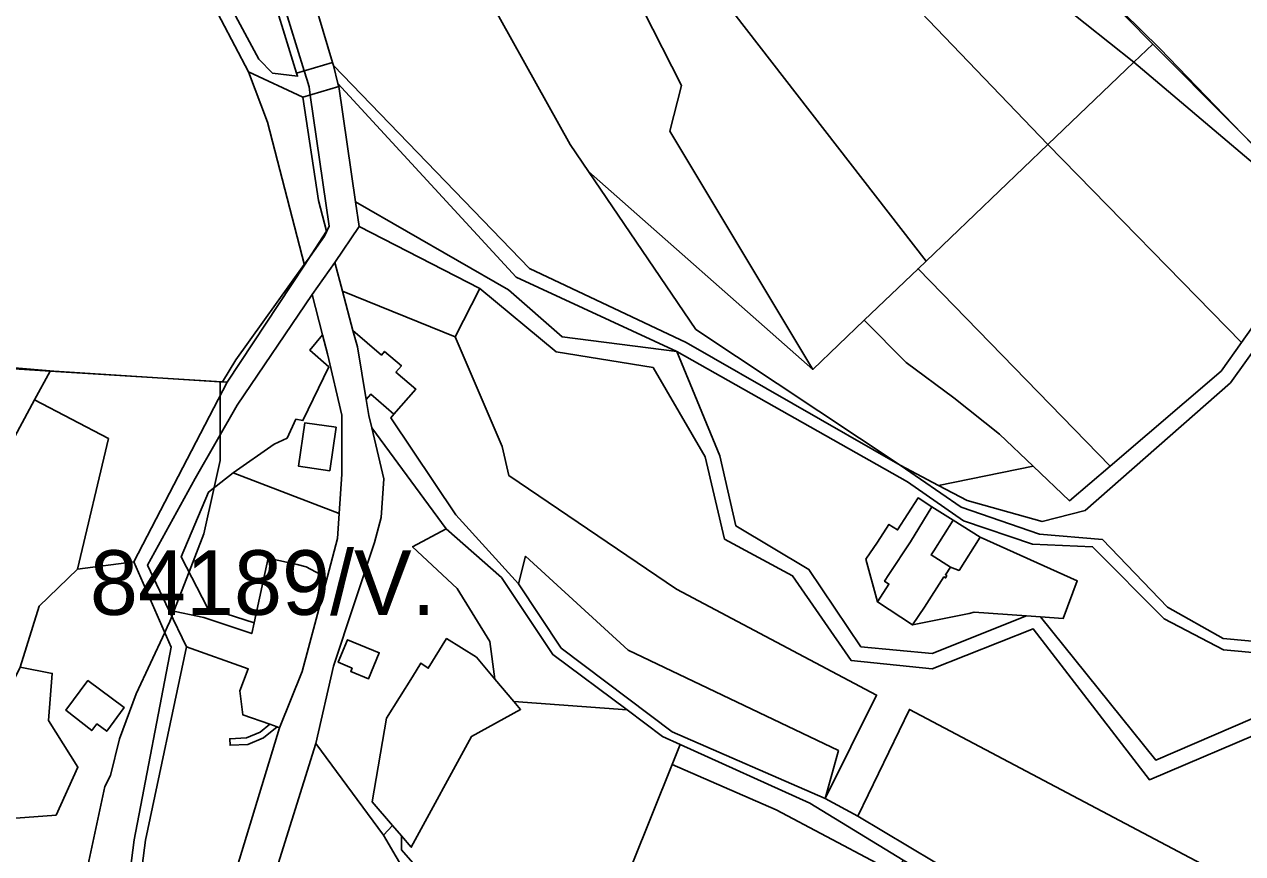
# Model space of a CAD drawing. Extents: x -477304 to -465429, y -1159113 to -1149210.
# Drawn here: x -471795.4 to -471512.5, y -1157437.1 to -1157244.4 of the extents above; entities that cross this region are included whole.
import ezdxf

# ---------------------------------------------------------------- set-up
doc = ezdxf.new("R2010")
doc.units = 0
for name, color, linetype in [('BPEJ_s', 7, 'Continuous'), ('orna_s', 7, 'Continuous'), ('ostatni_s', 7, 'Continuous'), ('PUPFL_s', 7, 'Continuous'), ('trav_porost_s', 7, 'Continuous'), ('voda_s', 7, 'Continuous')]:
    doc.layers.add(name, color=color, linetype=linetype)

msp = doc.modelspace()

# ---------------------------------------------------------------- linework, layer by layer
at = {"layer": 'BPEJ_s'}
for points in [[(-471595.75, -1157222.6), (-471575.33, -1157220.26), (-471562.35, -1157219.83), (-471553.07, -1157228.99), (-471531.73, -1157250.04), (-471512.53, -1157269.92), (-471503.21, -1157279.57), (-471473.45, -1157309.58), (-471461.33, -1157322.98), (-471426.88, -1157358.29), (-471406.67, -1157378.07), (-471393.7, -1157391.89)], [(-471553.07, -1157228.99), (-471531.73, -1157250.04), (-471512.53, -1157269.92), (-471503.21, -1157279.57)], [(-471805.02, -1157323.62), (-471788.61, -1157325.02), (-471750.01, -1157327.45), (-471749.43, -1157327.49), (-471746.32, -1157322.35), (-471730.42, -1157300.22), (-471729.08, -1157298.35), (-471725.69, -1157293.63), (-471724.63, -1157291.29), (-471729.03, -1157260.87), (-471729.31, -1157258.97), (-471729.85, -1157257.2), (-471730.44, -1157255.27), (-471736.96, -1157234.08)], [(-471781.62, -1157444.21), (-471776.73, -1157421.45), (-471775.46, -1157418.9), (-471773.33, -1157410.39), (-471769.5, -1157399.97), (-471762.82, -1157385.7), (-471762.24, -1157384.47), (-471761.63, -1157383.17), (-471761.17, -1157381.97), (-471760.7, -1157380.76), (-471757.19, -1157371.64), (-471753.76, -1157362.75), (-471751.35, -1157352.04), (-471749.93, -1157345.74), (-471749.93, -1157339.74), (-471749.93, -1157330.67), (-471749.93, -1157328.32), (-471749.98, -1157327.74), (-471750.01, -1157327.45), (-471749.43, -1157327.49), (-471746.32, -1157322.35), (-471730.42, -1157300.22), (-471729.08, -1157298.35), (-471725.69, -1157293.63), (-471724.63, -1157291.29), (-471729.03, -1157260.87), (-471729.31, -1157258.97), (-471729.85, -1157257.2), (-471730.44, -1157255.27), (-471736.96, -1157234.08)], [(-471854.44, -1157440.02), (-471852.36, -1157424.77), (-471850.75, -1157412.95), (-471840.57, -1157349.14), (-471838.62, -1157337.23), (-471838.44, -1157333.59), (-471838.2, -1157328.73), (-471837.7, -1157326.33), (-471837.13, -1157323.62), (-471835.64, -1157321.92), (-471805.02, -1157323.62), (-471788.61, -1157325.02), (-471750.01, -1157327.45)], [(-471750.01, -1157327.45), (-471749.98, -1157327.74), (-471749.93, -1157328.32), (-471749.93, -1157330.67), (-471749.93, -1157339.74), (-471749.93, -1157345.74), (-471751.35, -1157352.04), (-471753.76, -1157362.75), (-471757.19, -1157371.64), (-471760.7, -1157380.76), (-471761.17, -1157381.97), (-471761.63, -1157383.17), (-471762.24, -1157384.47), (-471762.82, -1157385.7), (-471769.5, -1157399.97), (-471773.33, -1157410.39), (-471775.46, -1157418.9), (-471776.73, -1157421.45), (-471781.62, -1157444.21)]]:
    msp.add_lwpolyline(points, dxfattribs=at)
at = {"layer": 'orna_s'}
for points in [[(-471600.35, -1157313.18), (-471612.26, -1157324.58), (-471645.5, -1157269.28), (-471642.83, -1157258.66), (-471651.72, -1157241.13), (-471650.33, -1157231.63), (-471639.48, -1157230.4), (-471585.99, -1157299.42), (-471587.86, -1157301.21)], [(-471561.13, -1157347.06), (-471568.98, -1157339.62), (-471579.55, -1157331.16), (-471590.64, -1157323), (-471600.35, -1157313.18), (-471587.86, -1157301.21), (-471543.22, -1157347.03), (-471552.66, -1157355.1)], [(-471797.77, -1157324.44), (-471789.45, -1157324.97), (-471793.09, -1157331.69), (-471803.48, -1157350.89), (-471806.62, -1157350.81)], [(-471819.17, -1157387.44), (-471806.62, -1157350.81), (-471803.48, -1157350.89), (-471793.09, -1157331.69), (-471775.92, -1157340.65), (-471783.1, -1157371), (-471791.97, -1157379.6), (-471796.43, -1157393.77), (-471814.25, -1157430.05), (-471822.37, -1157430.41), (-471825.93, -1157422.51), (-471832.66, -1157430.32), (-471842.89, -1157431.61)], [(-471644.97, -1157416.34), (-471620.85, -1157426.86), (-471597.46, -1157439.28), (-471609.69, -1157460.83), (-471611.65, -1157466.29), (-471624.94, -1157456.36), (-471637.72, -1157448.32), (-471654.29, -1157439.52)]]:
    msp.add_lwpolyline(points, close=True, dxfattribs=at)
at = {"layer": 'ostatni_s'}
for points in [[(-471750.7, -1157234.33), (-471740.99, -1157252.54), (-471737.77, -1157255.76), (-471731.99, -1157256.49), (-471732.21, -1157255.8), (-471723.89, -1157253.32), (-471723.65, -1157254), (-471722.6, -1157258.15), (-471722.41, -1157258.89), (-471730.75, -1157261.38), (-471743.41, -1157255.45), (-471752.92, -1157237.27)], [(-471498.34, -1157391.43), (-471516.9, -1157389.72), (-471530.69, -1157382.51), (-471547.34, -1157365.79), (-471561.3, -1157365.18), (-471577.28, -1157359.79), (-471590.29, -1157350.68), (-471643.9, -1157320.4), (-471681.2, -1157303.19), (-471722.6, -1157258.15), (-471723.65, -1157254), (-471678.13, -1157301.12), (-471641.71, -1157318.3), (-471592.05, -1157346.84), (-471577.82, -1157356.58), (-471559.67, -1157362.83), (-471545.05, -1157364.1), (-471529.9, -1157379.78), (-471517.02, -1157387.07), (-471497.65, -1157388.84)], [(-471750.11, -1157453.63), (-471736.15, -1157407.81), (-471730.94, -1157394.76), (-471726.22, -1157377.1), (-471722.68, -1157363.83), (-471722.29, -1157358.04), (-471721.67, -1157348.89), (-471721.66, -1157335.18), (-471725.06, -1157320.95), (-471726.2, -1157316.54), (-471728.58, -1157307.15), (-471723.31, -1157299.75), (-471721.54, -1157306.41), (-471719.11, -1157315.55), (-471718.09, -1157319.36), (-471716.05, -1157331.58), (-471715.43, -1157335.28), (-471714.74, -1157338.17), (-471711.9, -1157350.03), (-471712.57, -1157359.01), (-471714.07, -1157364.81), (-471723.6, -1157393.49), (-471727.71, -1157411.5), (-471742.03, -1157457.2)]]:
    msp.add_lwpolyline(points, dxfattribs=at)
for points in [[(-471722.41, -1157258.89), (-471722.6, -1157258.15), (-471681.2, -1157303.19), (-471643.9, -1157320.4), (-471670.49, -1157316.99), (-471682.99, -1157306.09), (-471718.53, -1157285.63)], [(-471689.63, -1157305.77), (-471695.37, -1157317.02), (-471721.54, -1157306.41), (-471723.31, -1157299.75), (-471717.69, -1157291.42)], [(-471543.22, -1157347.03), (-471517.46, -1157325.02), (-471512.71, -1157318.3), (-471502.81, -1157304.3), (-471500.07, -1157306.41), (-471515.26, -1157327.67), (-471549.07, -1157357.35), (-471559.01, -1157359.89), (-471576.42, -1157355.04), (-471583.09, -1157351.54), (-471561.13, -1157347.06), (-471552.66, -1157355.1)], [(-471730.74, -1157336.49), (-471732.35, -1157336.17), (-471734.42, -1157340.53), (-471737.39, -1157341.98), (-471746.97, -1157348.61), (-471752.65, -1157353.06), (-471759.02, -1157368.11), (-471752.89, -1157379.94), (-471742.08, -1157383.46), (-471742.62, -1157385.96), (-471753.72, -1157382.22), (-471761.87, -1157380.52), (-471766.8, -1157370.06), (-471755.75, -1157349.92), (-471746.03, -1157332.91), (-471728.58, -1157307.15), (-471726.2, -1157316.54), (-471729.12, -1157320.12), (-471724.72, -1157323.99)], [(-471591.29, -1157438.54), (-471613.03, -1157425.3), (-471643.09, -1157411.68), (-471647.18, -1157409.83), (-471655.43, -1157403.69), (-471672.7, -1157390.82), (-471684.63, -1157372.89), (-471697.43, -1157361.6), (-471714.74, -1157338.17), (-471715.43, -1157335.28), (-471716.05, -1157331.58), (-471714.99, -1157330.36), (-471709.58, -1157335.02), (-471710.29, -1157335.84), (-471695.2, -1157358.34), (-471680.63, -1157374.41), (-471670.72, -1157389.32), (-471644.99, -1157408.78), (-471609.44, -1157424.25), (-471601.84, -1157428.32), (-471536.26, -1157467.53), (-471531.84, -1157470.92), (-471532.78, -1157472.01)], [(-471724.49, -1157348.14), (-471731.75, -1157347.09), (-471730.28, -1157336.96), (-471723.03, -1157338.01)], [(-471726.65, -1157372.23), (-471729.98, -1157370.44), (-471732.06, -1157369.9), (-471738.8, -1157368.43), (-471739.58, -1157372), (-471742.08, -1157383.46), (-471752.89, -1157379.94), (-471759.02, -1157368.11), (-471752.65, -1157353.06), (-471746.97, -1157348.61), (-471722.29, -1157358.04), (-471722.68, -1157363.83), (-471726.22, -1157377.1)], [(-471581.2, -1157372.48), (-471581.46, -1157373.03), (-471581.84, -1157372.8), (-471586.35, -1157379.79), (-471589.11, -1157383.95), (-471597.26, -1157378.6), (-471594.61, -1157374.46), (-471595.65, -1157373.78), (-471594.64, -1157372.25), (-471589.59, -1157364.6), (-471584.63, -1157356.47), (-471579.68, -1157359.59), (-471584.2, -1157366.71), (-471584.82, -1157367.66), (-471580.35, -1157370.53), (-471581.5, -1157372.28)], [(-471739.58, -1157372), (-471738.8, -1157368.43), (-471732.06, -1157369.9), (-471729.98, -1157370.44), (-471726.65, -1157372.23), (-471726.22, -1157377.1), (-471730.94, -1157394.76), (-471736.15, -1157407.81), (-471736.73, -1157407.61), (-471738.39, -1157407.02), (-471744.71, -1157404.8), (-471745.4, -1157399.22), (-471743.44, -1157394.15), (-471757.78, -1157389.02), (-471761.87, -1157380.52), (-471753.72, -1157382.22), (-471742.62, -1157385.96), (-471742.08, -1157383.46)], [(-471715.49, -1157396.45), (-471719.64, -1157394.74), (-471719.33, -1157394), (-471722.54, -1157392.62), (-471720.37, -1157387.36), (-471712.99, -1157390.41)], [(-471691.59, -1157409.81), (-471705.57, -1157435.57), (-471707.87, -1157432.89), (-471709.92, -1157430.51), (-471714.62, -1157425.04), (-471711.34, -1157405.58), (-471705.28, -1157395.98), (-471703.33, -1157392.81), (-471701.64, -1157393.98), (-471697.35, -1157387.12), (-471690.41, -1157391.46), (-471686.12, -1157396.51), (-471681.72, -1157401.7), (-471680.16, -1157403.54)], [(-471778.59, -1157406.91), (-471779.77, -1157408.49), (-471785.79, -1157403.74), (-471780.65, -1157396.85), (-471772.22, -1157403.14), (-471776.31, -1157408.62)], [(-471698.6, -1157481.38), (-471697.92, -1157471.57), (-471723.04, -1157446.11), (-471735.54, -1157440.53), (-471743.9, -1157471.34), (-471747.27, -1157471.62), (-471742.03, -1157457.2), (-471727.71, -1157411.5), (-471712.04, -1157432.74), (-471687.37, -1157474.86), (-471676.72, -1157500.73), (-471668.85, -1157534.83), (-471678.3, -1157512.28), (-471689.7, -1157507.58), (-471688.32, -1157499.68)], [(-471676.72, -1157500.73), (-471687.37, -1157474.86), (-471712.04, -1157432.74), (-471709.92, -1157430.51), (-471707.87, -1157432.89), (-471707.84, -1157436.21), (-471692.47, -1157453.73), (-471673.84, -1157483.89), (-471670.06, -1157505.04), (-471622.06, -1157634.93), (-471639.34, -1157652.02), (-471662.42, -1157588.78), (-471668.85, -1157534.83)]]:
    msp.add_lwpolyline(points, close=True, dxfattribs=at)
at = {"layer": 'PUPFL_s'}
for points in [[(-471247.87, -1157496.21), (-471325.5, -1157460.09), (-471440.37, -1157342.39), (-471533.35, -1157249.01), (-471563.69, -1157218.21), (-471654.84, -1157226.07), (-471692.75, -1157229.08), (-471730.12, -1157232.17), (-471744.05, -1157220.16), (-471749.26, -1157215.67), (-471768.33, -1157211.35), (-471783.71, -1157212.42), (-471791.25, -1157210.9), (-471806.11, -1157198.23), (-471831.21, -1157186.83), (-471856.12, -1157184.54), (-471923.49, -1157140.7), (-471958.22, -1157107.83), (-471975.7, -1157085.58), (-471987.92, -1157051.4), (-472009.29, -1157017.07), (-472016.29, -1156972.29)], [(-472000.47, -1157055.81), (-471982.49, -1157091.95), (-471964.09, -1157113.59), (-471925.24, -1157151.43), (-471861.66, -1157190.58), (-471840.27, -1157199.12), (-471813.06, -1157203.36), (-471793.31, -1157220.43), (-471770.99, -1157221.99), (-471752.92, -1157237.27), (-471743.41, -1157255.45), (-471738.98, -1157267.18), (-471730.39, -1157300.35), (-471748.32, -1157327.56), (-471789.45, -1157324.97), (-471797.77, -1157324.44), (-471835.2, -1157322.06)], [(-471505.7, -1157403.77), (-471532.65, -1157415.33), (-471559.39, -1157382.07), (-471554.13, -1157382.44), (-471550.89, -1157373.7), (-471573.42, -1157363.52), (-471579.68, -1157359.59), (-471584.63, -1157356.47), (-471587.84, -1157354.45), (-471592.6, -1157361.88), (-471594.62, -1157360.58), (-471597.28, -1157364.71), (-471599.99, -1157368.63), (-471597.26, -1157378.6), (-471589.11, -1157383.95), (-471576, -1157381.25), (-471574.8, -1157381), (-471562.64, -1157381.84), (-471584.59, -1157390.59), (-471601.13, -1157389.03), (-471613.2, -1157371.05), (-471630.15, -1157360.94), (-471633.86, -1157344.65), (-471643.9, -1157320.4), (-471590.29, -1157350.68), (-471577.28, -1157359.79), (-471561.3, -1157365.18), (-471547.34, -1157365.79), (-471530.69, -1157382.51), (-471516.9, -1157389.72), (-471498.34, -1157391.43)]]:
    msp.add_lwpolyline(points, dxfattribs=at)
for points in [[(-471650.33, -1157231.63), (-471650.19, -1157230.68), (-471654.84, -1157226.07), (-471563.69, -1157218.21), (-471533.35, -1157249.01), (-471537.72, -1157253.19), (-471571.65, -1157226.17), (-471584.21, -1157224.25), (-471601.99, -1157226.16), (-471639.48, -1157230.4)], [(-471750.7, -1157234.33), (-471768.52, -1157219.42), (-471754.26, -1157219.55), (-471739.4, -1157232.33), (-471732.21, -1157255.8), (-471731.99, -1157256.49), (-471737.77, -1157255.76), (-471740.99, -1157252.54)], [(-471584.21, -1157224.25), (-471571.65, -1157226.17), (-471537.72, -1157253.19), (-471557.72, -1157272.34), (-471601.99, -1157226.16)], [(-471549.07, -1157357.35), (-471515.26, -1157327.67), (-471500.07, -1157306.41), (-471502.81, -1157304.3), (-471499.55, -1157287.13), (-471510, -1157276.65), (-471537.72, -1157253.19), (-471533.35, -1157249.01), (-471440.37, -1157342.39), (-471325.5, -1157460.09), (-471362.35, -1157449.02), (-471385.65, -1157432.75), (-471426.43, -1157417.31), (-471483.63, -1157398.8), (-471497.65, -1157388.84), (-471517.02, -1157387.07), (-471529.9, -1157379.78), (-471545.05, -1157364.1), (-471559.67, -1157362.83), (-471577.82, -1157356.58), (-471592.05, -1157346.84), (-471583.09, -1157351.54), (-471576.42, -1157355.04), (-471559.01, -1157359.89)], [(-471727.14, -1157285.34), (-471725.24, -1157292.49), (-471730.39, -1157300.35), (-471738.98, -1157267.18), (-471743.41, -1157255.45), (-471730.75, -1157261.38)], [(-471499.55, -1157287.13), (-471502.81, -1157304.3), (-471512.71, -1157318.3), (-471557.72, -1157272.34), (-471537.72, -1157253.19), (-471510, -1157276.65)], [(-471599.99, -1157368.63), (-471597.28, -1157364.71), (-471594.62, -1157360.58), (-471592.6, -1157361.88), (-471587.84, -1157354.45), (-471584.63, -1157356.47), (-471589.59, -1157364.6), (-471594.64, -1157372.25), (-471595.65, -1157373.78), (-471594.61, -1157374.46), (-471597.26, -1157378.6)], [(-471584.2, -1157366.71), (-471579.68, -1157359.59), (-471573.42, -1157363.52), (-471578.31, -1157371.27), (-471580.35, -1157370.53), (-471584.82, -1157367.66)], [(-471573.42, -1157363.52), (-471550.89, -1157373.7), (-471554.13, -1157382.44), (-471559.39, -1157382.07), (-471562.64, -1157381.84), (-471574.8, -1157381), (-471576, -1157381.25), (-471589.11, -1157383.95), (-471586.35, -1157379.79), (-471581.84, -1157372.8), (-471581.46, -1157373.03), (-471581.2, -1157372.48), (-471581.5, -1157372.28), (-471580.35, -1157370.53), (-471578.31, -1157371.27)]]:
    msp.add_lwpolyline(points, close=True, dxfattribs=at)
at = {"layer": 'trav_porost_s'}
for points in [[(-471651.72, -1157241.13), (-471642.83, -1157258.66), (-471645.5, -1157269.28), (-471612.26, -1157324.58), (-471664.41, -1157278.62), (-471668.69, -1157272.32), (-471692.75, -1157229.08), (-471654.84, -1157226.07), (-471650.19, -1157230.68), (-471650.33, -1157231.63)], [(-471601.99, -1157226.16), (-471557.72, -1157272.34), (-471585.99, -1157299.42), (-471639.48, -1157230.4)], [(-471692.75, -1157229.08), (-471668.69, -1157272.32), (-471664.41, -1157278.62), (-471639.49, -1157315.3), (-471592.05, -1157346.84), (-471641.71, -1157318.3), (-471678.13, -1157301.12), (-471723.65, -1157254), (-471723.89, -1157253.32), (-471730.12, -1157232.17)], [(-471512.71, -1157318.3), (-471517.46, -1157325.02), (-471543.22, -1157347.03), (-471587.86, -1157301.21), (-471585.99, -1157299.42), (-471557.72, -1157272.34)], [(-471590.64, -1157323), (-471579.55, -1157331.16), (-471568.98, -1157339.62), (-471561.13, -1157347.06), (-471583.09, -1157351.54), (-471592.05, -1157346.84), (-471639.49, -1157315.3), (-471664.41, -1157278.62), (-471612.26, -1157324.58), (-471600.35, -1157313.18)], [(-471679, -1157367.97), (-471680.63, -1157374.41), (-471695.2, -1157358.34), (-471710.29, -1157335.84), (-471709.58, -1157335.02), (-471704.53, -1157329.16), (-471709.12, -1157325.2), (-471707.86, -1157323.75), (-471711.76, -1157320.39), (-471712.5, -1157321.24), (-471719.11, -1157315.55), (-471721.54, -1157306.41), (-471695.37, -1157317.02), (-471684.45, -1157342.48), (-471682.88, -1157349.23), (-471643.94, -1157375.64), (-471597.5, -1157400.21), (-471609.44, -1157424.25), (-471606.37, -1157413.12), (-471655.19, -1157389.78)], [(-471726.2, -1157316.54), (-471725.06, -1157320.95), (-471721.66, -1157335.18), (-471721.67, -1157348.89), (-471722.29, -1157358.04), (-471746.97, -1157348.61), (-471737.39, -1157341.98), (-471734.42, -1157340.53), (-471732.35, -1157336.17), (-471730.74, -1157336.49), (-471724.72, -1157323.99), (-471729.12, -1157320.12)], [(-471716.05, -1157331.58), (-471718.09, -1157319.36), (-471719.11, -1157315.55), (-471712.5, -1157321.24), (-471711.76, -1157320.39), (-471707.86, -1157323.75), (-471709.12, -1157325.2), (-471704.53, -1157329.16), (-471709.58, -1157335.02), (-471714.99, -1157330.36)], [(-471783.1, -1157371), (-471775.92, -1157340.65), (-471793.09, -1157331.69), (-471789.45, -1157324.97), (-471748.32, -1157327.56), (-471770.02, -1157369.31)], [(-471723.03, -1157338.01), (-471730.28, -1157336.96), (-471731.75, -1157347.09), (-471724.49, -1157348.14)], [(-471711.34, -1157405.58), (-471714.62, -1157425.04), (-471709.92, -1157430.51), (-471712.04, -1157432.74), (-471727.71, -1157411.5), (-471723.6, -1157393.49), (-471714.07, -1157364.81), (-471712.57, -1157359.01), (-471711.9, -1157350.03), (-471714.74, -1157338.17), (-471697.43, -1157361.6), (-471705.28, -1157365.79), (-471694.89, -1157375.47), (-471687.31, -1157387.78), (-471686.12, -1157396.51), (-471690.41, -1157391.46), (-471697.35, -1157387.12), (-471701.64, -1157393.98), (-471703.33, -1157392.81), (-471705.28, -1157395.98)], [(-471681.72, -1157401.7), (-471686.12, -1157396.51), (-471687.31, -1157387.78), (-471694.89, -1157375.47), (-471705.28, -1157365.79), (-471697.43, -1157361.6), (-471684.63, -1157372.89), (-471672.7, -1157390.82), (-471655.43, -1157403.69)], [(-471680.63, -1157374.41), (-471679, -1157367.97), (-471655.19, -1157389.78), (-471606.37, -1157413.12), (-471609.44, -1157424.25), (-471644.99, -1157408.78), (-471670.72, -1157389.32)], [(-471814.25, -1157430.05), (-471788.08, -1157428.13), (-471783.01, -1157417), (-471789.81, -1157406.14), (-471788.94, -1157395.2), (-471796.43, -1157393.77), (-471791.97, -1157379.6), (-471783.1, -1157371), (-471770.02, -1157369.31), (-471761.32, -1157389.12), (-471769.94, -1157433.82), (-471772.74, -1157455.42), (-471791.21, -1157450.13), (-471799.57, -1157447.74), (-471817.92, -1157437.91)], [(-471722.54, -1157392.62), (-471719.33, -1157394), (-471719.64, -1157394.74), (-471715.49, -1157396.45), (-471712.99, -1157390.41), (-471720.37, -1157387.36)], [(-471757.78, -1157389.02), (-471743.44, -1157394.15), (-471745.4, -1157399.22), (-471744.71, -1157404.8), (-471738.39, -1157407.02), (-471740.68, -1157408.87), (-471743.86, -1157410.19), (-471747.74, -1157410.39), (-471747.66, -1157411.89), (-471743.52, -1157411.67), (-471739.9, -1157410.17), (-471736.73, -1157407.61), (-471736.15, -1157407.81), (-471750.11, -1157453.63), (-471759.58, -1157480.22), (-471761.04, -1157482.79), (-471761.66, -1157472.57), (-471770.07, -1157455.35), (-471767.27, -1157433.9)], [(-471789.81, -1157406.14), (-471783.01, -1157417), (-471788.08, -1157428.13), (-471814.25, -1157430.05), (-471796.43, -1157393.77), (-471788.94, -1157395.2)], [(-471772.22, -1157403.14), (-471780.65, -1157396.85), (-471785.79, -1157403.74), (-471779.77, -1157408.49), (-471778.59, -1157406.91), (-471776.31, -1157408.62)], [(-471670.06, -1157505.04), (-471673.84, -1157483.89), (-471692.47, -1157453.73), (-471707.84, -1157436.21), (-471707.87, -1157432.89), (-471705.57, -1157435.57), (-471691.59, -1157409.81), (-471680.16, -1157403.54), (-471681.72, -1157401.7), (-471655.43, -1157403.69), (-471647.18, -1157409.83), (-471643.09, -1157411.68), (-471644.97, -1157416.34), (-471654.29, -1157439.52), (-471637.72, -1157448.32), (-471624.94, -1157456.36), (-471611.65, -1157466.29), (-471619.63, -1157494.91), (-471617.95, -1157511.55), (-471622.05, -1157521.38)], [(-471589.88, -1157403.55), (-471522, -1157439.46), (-471536.26, -1157467.53), (-471601.84, -1157428.32)], [(-471738.39, -1157407.02), (-471736.73, -1157407.61), (-471739.9, -1157410.17), (-471743.52, -1157411.67), (-471747.66, -1157411.89), (-471747.74, -1157410.39), (-471743.86, -1157410.19), (-471740.68, -1157408.87)], [(-471622.05, -1157521.38), (-471617.95, -1157511.55), (-471619.63, -1157494.91), (-471611.65, -1157466.29), (-471609.69, -1157460.83), (-471597.46, -1157439.28), (-471620.85, -1157426.86), (-471644.97, -1157416.34), (-471643.09, -1157411.68), (-471613.03, -1157425.3), (-471591.29, -1157438.54), (-471600.71, -1157459.19), (-471614.84, -1157491.86), (-471612.53, -1157510.05), (-471618.62, -1157522.55)]]:
    msp.add_lwpolyline(points, close=True, dxfattribs=at)
msp.add_lwpolyline([(-471505.29, -1157473.28), (-471517.22, -1157482.14), (-471531.84, -1157470.92), (-471536.26, -1157467.53), (-471522, -1157439.46), (-471589.88, -1157403.55), (-471601.84, -1157428.32), (-471609.44, -1157424.25), (-471597.5, -1157400.21), (-471643.94, -1157375.64), (-471682.88, -1157349.23), (-471684.45, -1157342.48), (-471695.37, -1157317.02), (-471689.63, -1157305.77), (-471671.88, -1157320.52), (-471649.39, -1157324.16), (-471637.27, -1157344.86), (-471632.83, -1157363.99), (-471617, -1157372.52), (-471603.4, -1157392.19), (-471584.56, -1157394.17), (-471561.13, -1157384.83), (-471534.14, -1157419.89), (-471505.37, -1157407.66)], dxfattribs=at)
at = {"layer": 'voda_s'}
for points in [[(-471958.22, -1157107.83), (-471923.49, -1157140.7), (-471856.12, -1157184.54), (-471831.21, -1157186.83), (-471806.11, -1157198.23), (-471791.25, -1157210.9), (-471783.71, -1157212.42), (-471768.33, -1157211.35), (-471749.26, -1157215.67), (-471744.05, -1157220.16), (-471730.12, -1157232.17), (-471723.89, -1157253.32), (-471732.21, -1157255.8), (-471739.4, -1157232.33), (-471754.26, -1157219.55), (-471768.52, -1157219.42), (-471792.79, -1157216.73), (-471811.21, -1157201.13), (-471832.66, -1157191.55), (-471856.14, -1157190.27), (-471923.67, -1157147.83), (-471962.37, -1157110.62)], [(-471772.74, -1157455.42), (-471769.94, -1157433.82), (-471761.32, -1157389.12), (-471770.02, -1157369.31), (-471748.32, -1157327.56), (-471730.39, -1157300.35), (-471725.24, -1157292.49), (-471727.14, -1157285.34), (-471730.75, -1157261.38), (-471722.41, -1157258.89), (-471718.53, -1157285.63), (-471717.69, -1157291.42), (-471723.31, -1157299.75), (-471728.58, -1157307.15), (-471746.03, -1157332.91), (-471755.75, -1157349.92), (-471766.8, -1157370.06), (-471761.87, -1157380.52), (-471757.78, -1157389.02), (-471767.27, -1157433.9), (-471770.07, -1157455.35)], [(-471505.37, -1157407.66), (-471534.14, -1157419.89), (-471561.13, -1157384.83), (-471584.56, -1157394.17), (-471603.4, -1157392.19), (-471617, -1157372.52), (-471632.83, -1157363.99), (-471637.27, -1157344.86), (-471649.39, -1157324.16), (-471671.88, -1157320.52), (-471689.63, -1157305.77), (-471717.69, -1157291.42), (-471718.53, -1157285.63), (-471682.99, -1157306.09), (-471670.49, -1157316.99), (-471643.9, -1157320.4), (-471633.86, -1157344.65), (-471630.15, -1157360.94), (-471613.2, -1157371.05), (-471601.13, -1157389.03), (-471584.59, -1157390.59), (-471562.64, -1157381.84), (-471559.39, -1157382.07), (-471532.65, -1157415.33), (-471505.7, -1157403.77)]]:
    msp.add_lwpolyline(points, dxfattribs=at)

# ---------------------------------------------------------------- texts
at = {"layer": 'BPEJ_s'}
msp.add_text('84189/V.', height=15, dxfattribs=at).set_placement((-471780.21, -1157381.6))

doc.saveas('drawing.dxf')
